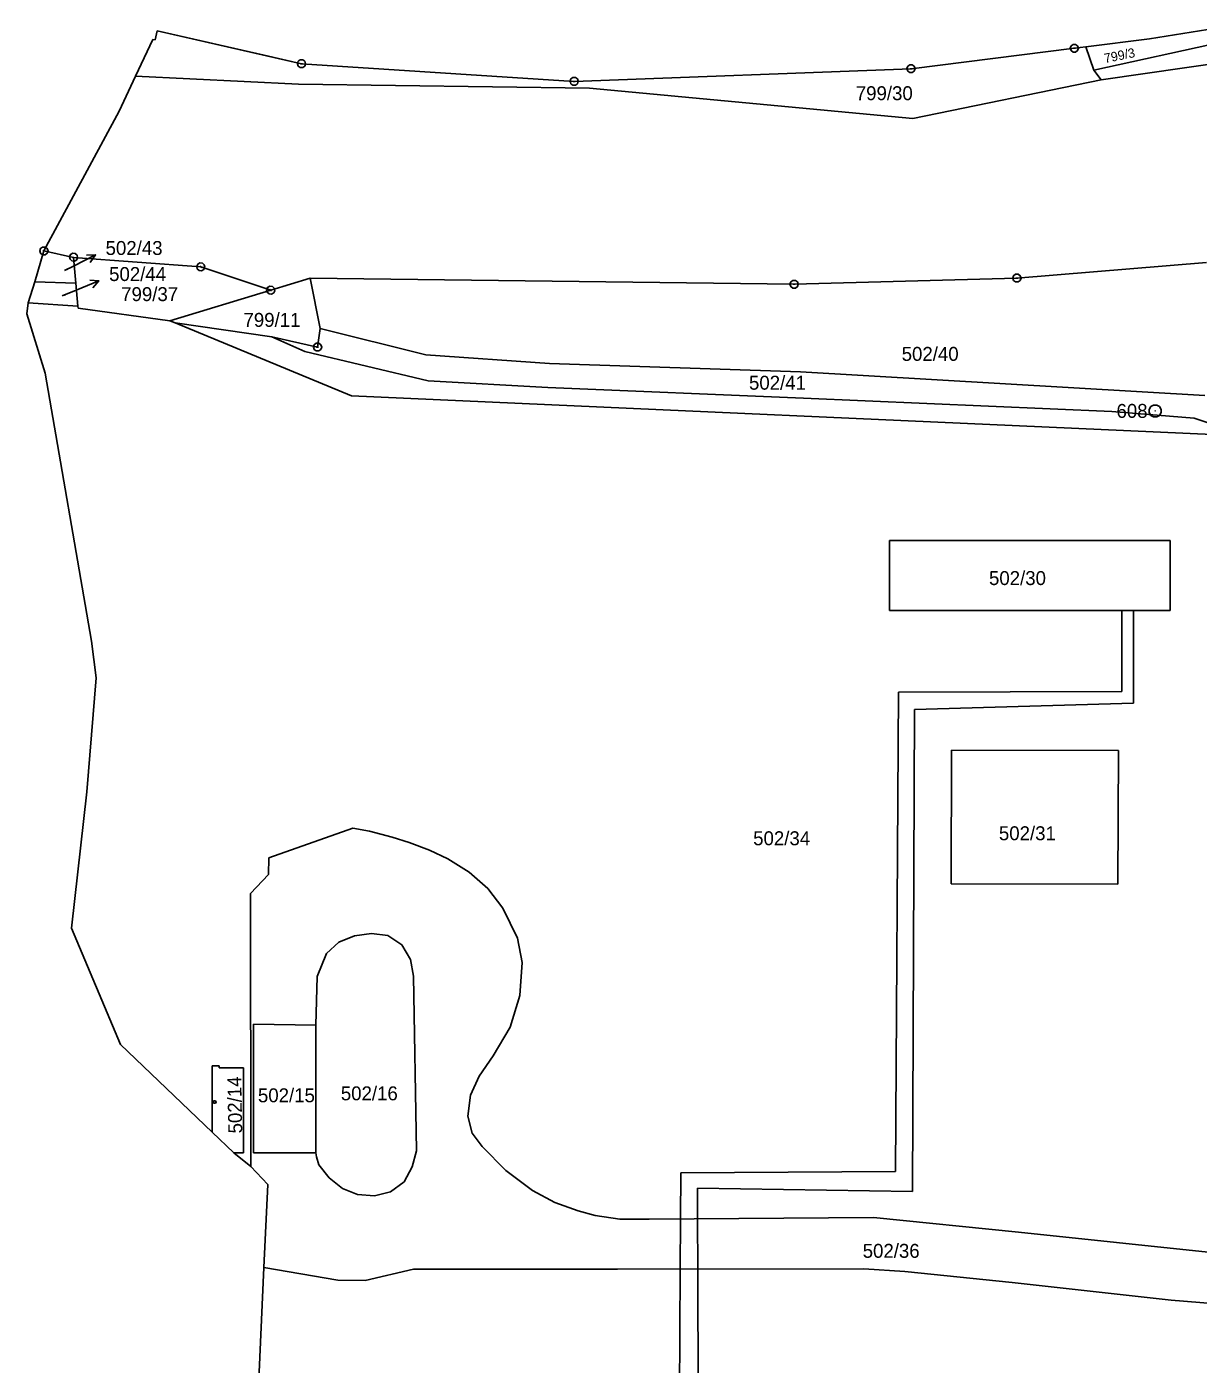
# Model space of a CAD drawing. Extents: x -759060 to -757386, y -1172273 to -1170948.
# Drawn here: x -758925.5 to -758782.5, y -1171825.9 to -1171662.7 of the extents above; entities that cross this region are included whole.
import ezdxf

# ---------------------------------------------------------------- set-up
doc = ezdxf.new("R2010")
doc.units = 0
for name, color, linetype in [('Vrstva 1', 7, 'Continuous'), ('Vrstva 11', 7, 'Continuous'), ('Vrstva 12', 7, 'Continuous'), ('Vrstva 13', 7, 'Continuous'), ('Vrstva 2', 7, 'Continuous'), ('Vrstva 5', 7, 'Continuous'), ('Vrstva 7', 7, 'Continuous'), ('Vrstva 8', 7, 'Continuous')]:
    doc.layers.add(name, color=color, linetype=linetype)

msp = doc.modelspace()

# ---------------------------------------------------------------- linework, layer by layer
at = {"layer": 'Vrstva 1'}
for p, q in [((-758909.85, -1171664.27), (-758909.6, -1171663.2)), ((-758896.55, -1171666.17), (-758909.6, -1171663.2)), ((-758788.45, -1171664.17), (-758779.31, -1171662.69)), ((-758912.26, -1171668.73), (-758910.16, -1171664.25)), ((-758910.16, -1171664.25), (-758909.85, -1171664.27)), ((-758817.58, -1171667.81), (-758797.64, -1171665.32)), ((-758797.64, -1171665.32), (-758796.25, -1171665.14)), ((-758796.25, -1171665.14), (-758788.45, -1171664.17)), ((-758795.27, -1171667.99), (-758796.25, -1171665.14)), ((-758795.27, -1171667.99), (-758779.69, -1171664.56)), ((-758767.97, -1171665.38), (-758794.37, -1171669.18)), ((-758896.55, -1171666.17), (-758891.99, -1171667.21)), ((-758891.99, -1171667.21), (-758858.7, -1171669.36)), ((-758914.25, -1171672.99), (-758912.26, -1171668.73)), ((-758892.35, -1171669.7), (-758912.26, -1171668.73)), ((-758858.7, -1171669.36), (-758817.58, -1171667.81)), ((-758794.37, -1171669.18), (-758795.27, -1171667.99)), ((-758892.35, -1171669.7), (-758856.83, -1171670.2)), ((-758856.83, -1171670.2), (-758817.35, -1171673.89)), ((-758817.35, -1171673.89), (-758794.37, -1171669.18)), ((-758923.44, -1171690.05), (-758914.25, -1171672.99)), ((-758923.44, -1171690.05), (-758924.57, -1171693.81)), ((-758923.44, -1171690.05), (-758919.83, -1171690.83)), ((-758919.83, -1171690.83), (-758904.3, -1171692)), ((-758919.83, -1171690.83), (-758919.54, -1171693.99)), ((-758781.51, -1171691.44), (-758804.65, -1171693.37)), ((-758904.3, -1171692), (-758895.76, -1171694.85)), ((-758890.93, -1171693.39), (-758895.76, -1171694.85)), ((-758890.93, -1171693.39), (-758889.72, -1171699.51)), ((-758831.85, -1171694.12), (-758890.93, -1171693.39)), ((-758804.65, -1171693.37), (-758831.85, -1171694.12)), ((-758924.57, -1171693.81), (-758925.35, -1171696.39)), ((-758919.54, -1171693.99), (-758924.57, -1171693.81)), ((-758919.54, -1171693.99), (-758919.29, -1171696.77)), ((-758895.76, -1171694.85), (-758908.07, -1171698.57)), ((-758925.35, -1171696.39), (-758925.54, -1171697.74)), ((-758919.29, -1171696.77), (-758925.35, -1171696.39)), ((-758919.26, -1171697.05), (-758919.29, -1171696.77)), ((-758923.31, -1171704.98), (-758925.54, -1171697.74)), ((-758908.07, -1171698.57), (-758919.26, -1171697.05)), ((-758908.07, -1171698.57), (-758907.43, -1171698.84)), ((-758907.43, -1171698.84), (-758895.61, -1171700.53)), ((-758907.43, -1171698.84), (-758885.9, -1171707.74)), ((-758889.72, -1171699.51), (-758890.03, -1171701.79)), ((-758876.82, -1171702.74), (-758889.72, -1171699.51)), ((-758895.61, -1171700.53), (-758891.59, -1171702.3)), ((-758890.03, -1171701.79), (-758895.61, -1171700.53)), ((-758891.59, -1171702.3), (-758876.55, -1171705.91)), ((-758861.7, -1171703.79), (-758876.82, -1171702.74)), ((-758831.06, -1171704.81), (-758861.7, -1171703.79)), ((-758781.7, -1171707.68), (-758831.06, -1171704.81)), ((-758917.62, -1171737.66), (-758923.31, -1171704.98)), ((-758876.55, -1171705.91), (-758861.92, -1171706.73)), ((-758885.9, -1171707.74), (-758780.79, -1171712.44)), ((-758861.92, -1171706.73), (-758830.69, -1171708.03)), ((-758830.69, -1171708.03), (-758793.05, -1171709.65)), ((-758793.05, -1171709.65), (-758783.01, -1171710.44)), ((-758783.01, -1171710.44), (-758778.62, -1171711.93)), ((-758820.22, -1171733.94), (-758820.19, -1171725.38)), ((-758820.19, -1171725.38), (-758785.93, -1171725.39)), ((-758785.93, -1171725.39), (-758785.94, -1171733.94)), ((-758785.94, -1171733.94), (-758820.22, -1171733.94)), ((-758917.08, -1171742.13), (-758917.62, -1171737.66)), ((-758918.22, -1171756.06), (-758917.08, -1171742.13)), ((-758812.65, -1171750.99), (-758812.67, -1171767.27)), ((-758792.27, -1171751.03), (-758812.65, -1171750.99)), ((-758792.32, -1171767.34), (-758792.27, -1171751.03)), ((-758920.09, -1171772.69), (-758918.22, -1171756.06)), ((-758885.74, -1171760.49), (-758895.99, -1171764.12)), ((-758883.71, -1171760.86), (-758885.74, -1171760.49)), ((-758880.91, -1171761.59), (-758883.71, -1171760.86)), ((-758878.84, -1171762.24), (-758880.91, -1171761.59)), ((-758876.38, -1171763.18), (-758878.84, -1171762.24)), ((-758874.14, -1171764.24), (-758876.38, -1171763.18)), ((-758895.99, -1171764.12), (-758896.01, -1171766.14)), ((-758871.52, -1171765.87), (-758874.14, -1171764.24)), ((-758896.01, -1171766.14), (-758898.21, -1171768.47)), ((-758869.23, -1171767.84), (-758871.52, -1171765.87)), ((-758898.21, -1171768.47), (-758898.18, -1171801.77)), ((-758867.41, -1171770.27), (-758869.23, -1171767.84)), ((-758812.67, -1171767.27), (-758792.32, -1171767.34)), ((-758865.63, -1171773.91), (-758867.41, -1171770.27)), ((-758914.11, -1171786.9), (-758920.09, -1171772.69)), ((-758883.46, -1171773.34), (-758885.51, -1171773.62)), ((-758881.46, -1171773.59), (-758883.46, -1171773.34)), ((-758887.44, -1171774.4), (-758888.94, -1171775.79)), ((-758885.51, -1171773.62), (-758887.44, -1171774.4)), ((-758879.75, -1171774.74), (-758881.46, -1171773.59)), ((-758878.68, -1171776.51), (-758879.75, -1171774.74)), ((-758865.05, -1171776.87), (-758865.63, -1171773.91)), ((-758888.94, -1171775.79), (-758890.08, -1171778.58)), ((-758878.33, -1171778.54), (-758878.68, -1171776.51)), ((-758865.34, -1171780.91), (-758865.05, -1171776.87)), ((-758890.08, -1171778.58), (-758890.23, -1171784.54)), ((-758877.97, -1171799.85), (-758878.33, -1171778.54)), ((-758866.54, -1171784.76), (-758865.34, -1171780.91)), ((-758897.87, -1171784.41), (-758897.85, -1171800.12)), ((-758897.87, -1171784.41), (-758890.23, -1171784.54)), ((-758890.23, -1171784.54), (-758890.24, -1171800.11)), ((-758868.58, -1171788.26), (-758866.54, -1171784.76)), ((-758902.91, -1171797.6), (-758914.11, -1171786.9)), ((-758902.91, -1171797.6), (-758902.9, -1171789.49)), ((-758902.9, -1171789.49), (-758902.03, -1171789.49)), ((-758902.03, -1171789.49), (-758902.04, -1171789.75)), ((-758902.04, -1171789.75), (-758899.07, -1171789.75)), ((-758899.07, -1171789.75), (-758899.07, -1171800.12)), ((-758870.31, -1171790.76), (-758868.58, -1171788.26)), ((-758871.35, -1171793.09), (-758870.31, -1171790.76)), ((-758871.7, -1171795.65), (-758871.35, -1171793.09)), ((-758871.16, -1171797.69), (-758871.7, -1171795.65)), ((-758900.25, -1171800.12), (-758902.91, -1171797.6)), ((-758869.94, -1171799.34), (-758871.16, -1171797.69)), ((-758867.06, -1171802.26), (-758869.94, -1171799.34)), ((-758898.18, -1171801.77), (-758900.25, -1171800.12)), ((-758899.07, -1171800.12), (-758900.25, -1171800.12)), ((-758897.85, -1171800.12), (-758890.24, -1171800.11)), ((-758890.24, -1171800.11), (-758890.15, -1171800.6)), ((-758890.15, -1171800.6), (-758889.86, -1171801.58)), ((-758878.47, -1171801.83), (-758877.97, -1171799.85)), ((-758896.12, -1171803.97), (-758898.18, -1171801.77)), ((-758889.86, -1171801.58), (-758888.62, -1171803.18)), ((-758879.47, -1171803.63), (-758878.47, -1171801.83)), ((-758863.78, -1171804.7), (-758867.06, -1171802.26)), ((-758896.58, -1171814.1), (-758896.12, -1171803.97)), ((-758888.62, -1171803.18), (-758886.99, -1171804.48)), ((-758886.99, -1171804.48), (-758885.16, -1171805.21)), ((-758881.12, -1171804.85), (-758879.47, -1171803.63)), ((-758885.16, -1171805.21), (-758883.09, -1171805.37)), ((-758883.09, -1171805.37), (-758881.12, -1171804.85)), ((-758861.07, -1171806.15), (-758863.78, -1171804.7)), ((-758858.2, -1171807.2), (-758861.07, -1171806.15)), ((-758856.16, -1171807.74), (-758858.2, -1171807.2)), ((-758853.15, -1171808.21), (-758856.16, -1171807.74)), ((-758849.56, -1171808.22), (-758853.15, -1171808.21)), ((-758822.16, -1171808), (-758849.56, -1171808.22)), ((-758804.48, -1171809.81), (-758822.16, -1171808)), ((-758780.52, -1171812.32), (-758804.48, -1171809.81)), ((-758896.58, -1171814.1), (-758898.14, -1171847.8)), ((-758887.54, -1171815.65), (-758896.58, -1171814.1)), ((-758878.32, -1171814.3), (-758884.24, -1171815.67)), ((-758853.42, -1171814.32), (-758878.32, -1171814.3)), ((-758823.34, -1171814.25), (-758853.42, -1171814.32)), ((-758818.34, -1171814.57), (-758823.34, -1171814.25)), ((-758884.24, -1171815.67), (-758887.54, -1171815.65)), ((-758805.25, -1171815.95), (-758818.34, -1171814.57)), ((-758785.82, -1171818.1), (-758805.25, -1171815.95)), ((-758785.82, -1171818.1), (-758726.85, -1171822.75))]:
    msp.add_line(p, q, dxfattribs=at)
at = {"layer": 'Vrstva 11'}
for p, q in [((-758909.85, -1171664.27), (-758909.6, -1171663.2)), ((-758909.6, -1171663.2), (-758891.99, -1171667.21)), ((-758788.45, -1171664.17), (-758779.31, -1171662.69)), ((-758912.26, -1171668.73), (-758910.16, -1171664.25)), ((-758910.16, -1171664.25), (-758909.85, -1171664.27)), ((-758817.58, -1171667.81), (-758797.64, -1171665.32)), ((-758797.64, -1171665.32), (-758796.25, -1171665.14)), ((-758796.25, -1171665.14), (-758788.45, -1171664.17)), ((-758891.99, -1171667.21), (-758858.7, -1171669.36)), ((-758914.25, -1171672.99), (-758912.26, -1171668.73)), ((-758858.7, -1171669.36), (-758817.58, -1171667.81)), ((-758923.44, -1171690.05), (-758914.25, -1171672.99)), ((-758924.57, -1171693.81), (-758923.44, -1171690.05)), ((-758925.35, -1171696.39), (-758924.57, -1171693.81)), ((-758925.54, -1171697.74), (-758925.35, -1171696.39)), ((-758923.31, -1171704.98), (-758925.54, -1171697.74)), ((-758917.62, -1171737.66), (-758923.31, -1171704.98)), ((-758917.08, -1171742.13), (-758917.62, -1171737.66)), ((-758918.22, -1171756.06), (-758917.08, -1171742.13)), ((-758920.09, -1171772.69), (-758918.22, -1171756.06)), ((-758914.11, -1171786.9), (-758920.09, -1171772.69)), ((-758902.91, -1171797.6), (-758914.11, -1171786.9)), ((-758900.25, -1171800.12), (-758902.91, -1171797.6)), ((-758898.18, -1171801.77), (-758900.25, -1171800.12)), ((-758896.12, -1171803.97), (-758898.18, -1171801.77)), ((-758896.58, -1171814.1), (-758896.12, -1171803.97)), ((-758898.14, -1171847.8), (-758896.58, -1171814.1))]:
    msp.add_line(p, q, dxfattribs=at)
at = {"layer": 'Vrstva 12'}
for p, q in [((-758902.91, -1171797.6), (-758902.9, -1171789.49)), ((-758902.9, -1171789.49), (-758902.03, -1171789.49)), ((-758902.03, -1171789.49), (-758902.04, -1171789.75)), ((-758902.04, -1171789.75), (-758899.07, -1171789.75)), ((-758899.07, -1171789.75), (-758899.07, -1171800.12)), ((-758900.25, -1171800.12), (-758902.91, -1171797.6)), ((-758899.07, -1171800.12), (-758900.25, -1171800.12))]:
    msp.add_line(p, q, dxfattribs=at)
at = {"layer": 'Vrstva 13'}
for p, q in [((-758791.85, -1171743.8), (-758791.86, -1171733.94)), ((-758791.86, -1171733.94), (-758790.44, -1171733.94)), ((-758790.44, -1171733.94), (-758790.44, -1171745.23)), ((-758819.47, -1171802.4), (-758819.13, -1171743.88)), ((-758819.13, -1171743.88), (-758791.85, -1171743.8)), ((-758790.44, -1171745.23), (-758817.14, -1171746.01)), ((-758817.14, -1171746.01), (-758817.4, -1171804.84)), ((-758845.73, -1171808.19), (-758845.7, -1171802.54)), ((-758845.7, -1171802.54), (-758819.47, -1171802.4)), ((-758817.4, -1171804.84), (-758843.65, -1171804.42)), ((-758843.65, -1171804.42), (-758843.64, -1171808.17)), ((-758845.77, -1171814.3), (-758845.73, -1171808.19)), ((-758843.64, -1171808.17), (-758843.62, -1171814.25)), ((-758845.94, -1171845.5), (-758845.77, -1171814.3)), ((-758843.62, -1171814.25), (-758843.51, -1171845.55))]:
    msp.add_line(p, q, dxfattribs=at)
at = {"layer": 'Vrstva 5'}
msp.add_lwpolyline([(-758902.5, -1171793.76), (-758902.41, -1171793.91), (-758902.5, -1171794.06), (-758902.68, -1171794.06), (-758902.77, -1171793.91), (-758902.68, -1171793.76)], close=True, dxfattribs=at)
at = {"layer": 'Vrstva 7'}
for p, q in [((-758917.145, -1171690.542), (-758919.82, -1171691.9)), ((-758920.91, -1171692.45), (-758919.82, -1171691.9)), ((-758921.22, -1171695.54), (-758919.5, -1171694.84)), ((-758916.719, -1171693.714), (-758919.5, -1171694.84))]:
    msp.add_line(p, q, dxfattribs=at)
for points in [[(-758918.263, -1171690.549), (-758917.145, -1171690.542), (-758917.81, -1171691.441)], [(-758917.834, -1171693.626), (-758916.719, -1171693.714), (-758917.459, -1171694.553)]]:
    msp.add_lwpolyline(points, dxfattribs=at)
at = {"layer": 'Vrstva 8'}
for p, q in [((-758797.76, -1171665.32), (-758797.52, -1171665.32)), ((-758892.11, -1171667.21), (-758891.87, -1171667.21)), ((-758817.7, -1171667.81), (-758817.46, -1171667.81)), ((-758858.82, -1171669.36), (-758858.58, -1171669.36)), ((-758923.56, -1171690.05), (-758923.32, -1171690.05)), ((-758919.919, -1171690.749), (-758919.741, -1171690.911)), ((-758904.389, -1171691.919), (-758904.211, -1171692.081)), ((-758804.77, -1171693.37), (-758804.53, -1171693.37)), ((-758895.849, -1171694.769), (-758895.671, -1171694.931)), ((-758831.97, -1171694.12), (-758831.73, -1171694.12)), ((-758890.15, -1171701.79), (-758889.91, -1171701.79)), ((-758787.83, -1171709.57), (-758787.73, -1171709.57))]:
    msp.add_line(p, q, dxfattribs=at)
for points in [[(-758797.49, -1171664.84), (-758797.24, -1171665.02), (-758797.14, -1171665.31), (-758797.24, -1171665.6), (-758797.49, -1171665.78), (-758797.8, -1171665.78), (-758798.05, -1171665.6), (-758798.15, -1171665.31), (-758798.05, -1171665.02), (-758797.8, -1171664.84)], [(-758891.84, -1171666.73), (-758891.59, -1171666.91), (-758891.49, -1171667.2), (-758891.59, -1171667.49), (-758891.84, -1171667.67), (-758892.15, -1171667.67), (-758892.4, -1171667.49), (-758892.5, -1171667.2), (-758892.4, -1171666.91), (-758892.15, -1171666.73)], [(-758817.43, -1171667.33), (-758817.18, -1171667.51), (-758817.08, -1171667.8), (-758817.18, -1171668.09), (-758817.43, -1171668.27), (-758817.74, -1171668.27), (-758817.99, -1171668.09), (-758818.09, -1171667.8), (-758817.99, -1171667.51), (-758817.74, -1171667.33)], [(-758858.55, -1171668.88), (-758858.3, -1171669.06), (-758858.2, -1171669.35), (-758858.3, -1171669.64), (-758858.55, -1171669.82), (-758858.86, -1171669.82), (-758859.11, -1171669.64), (-758859.21, -1171669.35), (-758859.11, -1171669.06), (-758858.86, -1171668.88)], [(-758923.29, -1171689.57), (-758923.04, -1171689.75), (-758922.94, -1171690.04), (-758923.04, -1171690.33), (-758923.29, -1171690.51), (-758923.6, -1171690.51), (-758923.85, -1171690.33), (-758923.95, -1171690.04), (-758923.85, -1171689.75), (-758923.6, -1171689.57)], [(-758919.396, -1171690.575), (-758919.332, -1171690.877), (-758919.453, -1171691.159), (-758919.722, -1171691.306), (-758920.028, -1171691.271), (-758920.258, -1171691.063), (-758920.322, -1171690.762), (-758920.201, -1171690.48), (-758919.932, -1171690.332), (-758919.626, -1171690.367)], [(-758903.866, -1171691.745), (-758903.802, -1171692.047), (-758903.923, -1171692.329), (-758904.192, -1171692.476), (-758904.498, -1171692.441), (-758904.728, -1171692.233), (-758904.792, -1171691.932), (-758904.671, -1171691.65), (-758904.402, -1171691.502), (-758904.096, -1171691.537)], [(-758804.5, -1171692.89), (-758804.25, -1171693.07), (-758804.15, -1171693.36), (-758804.25, -1171693.65), (-758804.5, -1171693.83), (-758804.81, -1171693.83), (-758805.06, -1171693.65), (-758805.16, -1171693.36), (-758805.06, -1171693.07), (-758804.81, -1171692.89)], [(-758895.326, -1171694.595), (-758895.262, -1171694.897), (-758895.383, -1171695.179), (-758895.652, -1171695.326), (-758895.958, -1171695.291), (-758896.188, -1171695.083), (-758896.252, -1171694.782), (-758896.131, -1171694.5), (-758895.862, -1171694.352), (-758895.556, -1171694.387)], [(-758831.7, -1171693.64), (-758831.45, -1171693.82), (-758831.35, -1171694.11), (-758831.45, -1171694.4), (-758831.7, -1171694.58), (-758832.01, -1171694.58), (-758832.26, -1171694.4), (-758832.36, -1171694.11), (-758832.26, -1171693.82), (-758832.01, -1171693.64)], [(-758889.88, -1171701.31), (-758889.63, -1171701.49), (-758889.53, -1171701.78), (-758889.63, -1171702.07), (-758889.88, -1171702.25), (-758890.19, -1171702.25), (-758890.44, -1171702.07), (-758890.54, -1171701.78), (-758890.44, -1171701.49), (-758890.19, -1171701.31)], [(-758787.59, -1171708.85), (-758787.25, -1171709.04), (-758787.06, -1171709.38), (-758787.06, -1171709.77), (-758787.25, -1171710.11), (-758787.59, -1171710.3), (-758787.98, -1171710.3), (-758788.32, -1171710.11), (-758788.51, -1171709.77), (-758788.51, -1171709.38), (-758788.32, -1171709.04), (-758787.98, -1171708.85)]]:
    msp.add_lwpolyline(points, close=True, dxfattribs=at)

# ---------------------------------------------------------------- texts
at = {"layer": 'Vrstva 2'}
for s, height, rotation, p in [('799/3', 1.14, 11.34456, (-758793.894, -1171667.129)), ('502/14', 1.7, 91.10029, (-758899.225, -1171797.723))]:
    msp.add_text(s, height=height, rotation=rotation, dxfattribs=at).set_placement(p)
for s, height, p in [('799/30', 1.7, (-758824.323, -1171671.65)), ('502/43', 0.1, (-758920.896, -1171692.45)), ('799/37', 1.7, (-758914.009, -1171696.17)), ('502/44', 0.1, (-758921.206, -1171695.54)), ('799/11', 1.7, (-758899.076, -1171699.31)), ('502/40', 1.7, (-758818.723, -1171703.46)), ('502/41', 1.7, (-758837.363, -1171706.98)), ('502/30', 1.7, (-758808.063, -1171730.82)), ('502/31', 1.7, (-758806.853, -1171761.96)), ('502/34', 1.7, (-758836.853, -1171762.57)), ('502/15', 1.7, (-758897.313, -1171793.94)), ('502/16', 1.7, (-758887.193, -1171793.7)), ('502/36', 1.7, (-758823.483, -1171812.92))]:
    msp.add_text(s, height=height, dxfattribs=at).set_placement(p)
at = {"layer": 'Vrstva 7'}
for s, p in [('502/43', (-758915.913, -1171690.54)), ('502/44', (-758915.483, -1171693.72))]:
    msp.add_text(s, height=1.7, dxfattribs=at).set_placement(p)
at = {"layer": 'Vrstva 8'}
msp.add_text('608', height=1.7, dxfattribs=at).set_placement((-758792.497, -1171710.42))

doc.saveas('drawing.dxf')
